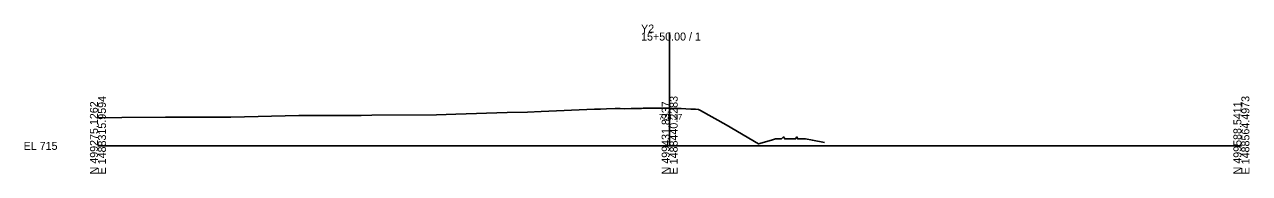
# Model space of a CAD drawing. Extents: x -26 to 1488809, y -10 to 499333.
# Drawn here: x -25.7 to 402.8, y 5490.3 to 5542.5 of the extents above; entities that cross this region are included whole.
import ezdxf

# ---------------------------------------------------------------- set-up
doc = ezdxf.new("R2010")
doc.units = 0
for name, color, linetype in [('Default', 7, 'Continuous'), ('Exist Cross Section Cell', 7, 'Continuous'), ('Exist XS Center Line Elevation Label', 7, 'Continuous'), ('Exist XS Ground Line', 7, 'Continuous')]:
    doc.layers.add(name, color=color, linetype=linetype)

msp = doc.modelspace()

# ---------------------------------------------------------------- linework, layer by layer
at = {"layer": 'Exist Cross Section Cell'}
for p, q in [((200, 5500), (200, 5539.7)), ((0, 5500), (200, 5500)), ((200, 5500), (400, 5500))]:
    msp.add_line(p, q, dxfattribs=at)
at = {"layer": 'Exist XS Ground Line'}
msp.add_lwpolyline([(0, 5509.87), (8.36, 5509.92), (23.65, 5510.05), (38.26, 5510.09), (46.52, 5510.06), (70.25, 5510.6), (75.88, 5510.65), (92.11, 5510.69), (95.83, 5510.74), (118.45, 5510.88), (125.17, 5511.16), (143.21, 5511.65), (150.31, 5511.85), (155, 5512.02), (173.73, 5512.83), (175.83, 5512.9), (177.87, 5512.99), (180.98, 5513.06), (182.65, 5513.04), (184.28, 5512.93), (186.52, 5513.04), (190.12, 5513.12), (190.75, 5513.18), (191.59, 5513.22), (193.19, 5513.23), (194.47, 5513.23), (194.97, 5513.23), (195.61, 5513.23), (196.75, 5513.21), (197.66, 5513.2), (198.53, 5513.19), (199.04, 5513.19), (199.75, 5513.17), (200.31, 5513.16), (200.85, 5513.14), (202.09, 5513.1), (204.04, 5513.04), (205.65, 5512.98), (207.43, 5512.91), (209.08, 5512.84), (210.03, 5512.73), (210.8, 5512.44), (219.79, 5507.35), (231.08, 5500.66), (235.68, 5502.04), (237.06, 5502.44), (239.09, 5502.43), (239.86, 5503.14), (240.25, 5502.43), (240.81, 5502.43), (241.61, 5502.44), (243.63, 5502.45), (244.05, 5502.45), (244.5, 5503.14), (244.82, 5502.46), (246.84, 5502.47), (247.48, 5502.47), (249.96, 5501.96), (254.12, 5501.18)], dxfattribs=at)

# ---------------------------------------------------------------- texts
at = {"layer": 'Default'}
msp.add_text('-', height=0.0001, dxfattribs=at).set_placement((0, 5500))
at = {"layer": 'Exist Cross Section Cell'}
for s, p in [('Y2', (190, 5539.7)), ('15+50.00 / 1', (190, 5536.9)), ('EL 715', (-26, 5498.6))]:
    msp.add_text(s, height=2.8, dxfattribs=at).set_placement(p)
for s, p in [('N 499275.1262', (0, 5490)), ('E 1488315.9594', (2.8, 5490)), ('N 499431.8337', (200, 5490)), ('E 1488440.2283', (202.8, 5490)), ('N 499588.5411', (400, 5490)), ('E 1488564.4973', (402.8, 5490))]:
    msp.add_text(s, height=2.8, rotation=90, dxfattribs=at).set_placement(p)
at = {"layer": 'Exist XS Center Line Elevation Label'}
msp.add_text('728.17', height=2, dxfattribs=at).set_placement((196.22, 5509.17))

doc.saveas('drawing.dxf')
